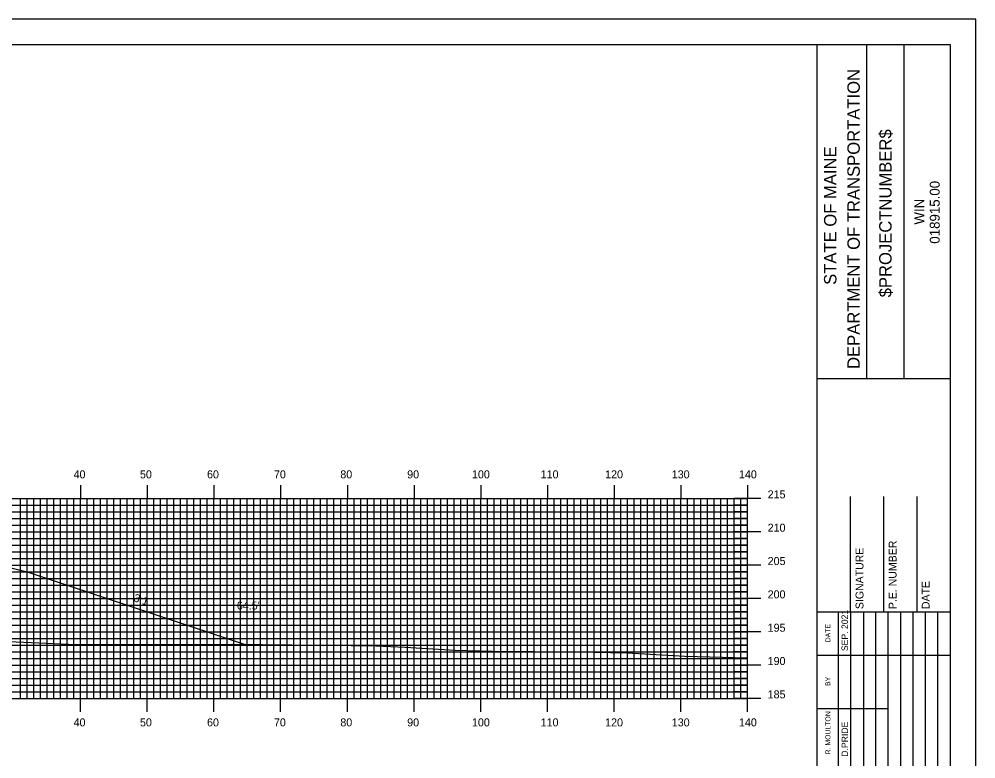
# Model space of a CAD drawing. Extents: x 1806651 to 1806995, y 442591 to 442811.
# Drawn here: x 1806848.1 to 1806991.5, y 442699.6 to 442810.5 of the extents above; entities that cross this region are included whole.
import ezdxf

# ---------------------------------------------------------------- set-up
doc = ezdxf.new("R2010")
doc.units = 0
for name, color, linetype in [('ANNOTATION', 7, 'Continuous'), ('BORDER', 7, 'Continuous'), ('D_Roadway_Centerline', 7, 'Continuous'), ('D_Roadway_SlopeLines', 7, 'Continuous'), ('D_Text_Standard', 7, 'Continuous'), ('H_V ANNOTATION', 7, 'Continuous'), ('MAJOR', 7, 'Continuous'), ('MINOR', 7, 'Continuous'), ('PLOT BOUNDARY', 7, 'Continuous'), ('S_Roadway_Centerline', 7, 'Continuous')]:
    doc.layers.add(name, color=color, linetype=linetype)

msp = doc.modelspace()

# ---------------------------------------------------------------- linework, layer by layer
at = {"layer": 'BORDER'}
for p, q in [((1806967.65, 442596.67), (1806967.65, 442806.67)), ((1806975.1, 442756.66), (1806975.1, 442806.66)), ((1806980.69, 442756.66), (1806980.69, 442806.66)), ((1806967.65, 442756.65), (1806987.65, 442756.65)), ((1806972.65, 442721.67), (1806972.65, 442738.97)), ((1806977.65, 442721.67), (1806977.65, 442738.97)), ((1806982.65, 442721.67), (1806982.65, 442738.97)), ((1806967.65, 442721.67), (1806987.65, 442721.67))]:
    msp.add_line(p, q, dxfattribs=at)
msp.add_lwpolyline([(1806667.65, 442596.67), (1806987.65, 442596.67), (1806987.65, 442806.67), (1806667.65, 442806.67)], close=True, dxfattribs=at)
for points in [[(1806970.88, 442715.17), (1806970.88, 442721.67)], [(1806972.74, 442686.68), (1806972.74, 442721.67)], [(1806974.6, 442721.67), (1806974.6, 442686.68)], [(1806976.47, 442686.68), (1806976.47, 442721.67)], [(1806978.33, 442686.68), (1806978.33, 442721.67)], [(1806980.19, 442686.68), (1806980.19, 442721.67)], [(1806982.06, 442686.68), (1806982.06, 442721.67)], [(1806983.92, 442686.68), (1806983.92, 442721.67)], [(1806985.78, 442686.68), (1806985.78, 442721.67)], [(1806970.88, 442686.68), (1806970.88, 442720.26)], [(1806967.65, 442715.17), (1806987.65, 442715.17)], [(1806967.65, 442707.17), (1806970.88, 442707.17)], [(1806970.88, 442707.17), (1806978.33, 442707.17)]]:
    msp.add_lwpolyline(points, dxfattribs=at)
at = {"layer": 'D_Roadway_Centerline'}
msp.add_lwpolyline([(1806757.75, 442718.48), (1806785.25, 442727.65), (1806787.07, 442728.1), (1806797.25, 442730.65), (1806805.25, 442730.97), (1806817.25, 442731.21), (1806829.25, 442730.97), (1806837.25, 442730.65), (1806847.42, 442728.1), (1806849.25, 442727.65), (1806881.77, 442716.8)], dxfattribs=at)
at = {"layer": 'D_Roadway_SlopeLines'}
msp.add_lwpolyline([(1806837.25, 442730.65), (1806849.25, 442727.65), (1806881.77, 442716.8)], dxfattribs=at)
at = {"layer": 'MAJOR'}
for p, q in [((1806857.25, 442740.67), (1806857.25, 442738.67)), ((1806867.25, 442740.67), (1806867.25, 442738.67)), ((1806877.25, 442740.67), (1806877.25, 442738.67)), ((1806887.25, 442740.67), (1806887.25, 442738.67)), ((1806897.25, 442740.67), (1806897.25, 442738.67)), ((1806907.25, 442740.67), (1806907.25, 442738.67)), ((1806917.25, 442740.67), (1806917.25, 442738.67)), ((1806927.25, 442740.67), (1806927.25, 442738.67)), ((1806937.25, 442740.67), (1806937.25, 442738.67)), ((1806947.25, 442740.67), (1806947.25, 442738.67)), ((1806957.25, 442740.67), (1806957.25, 442738.67)), ((1806677.25, 442738.67), (1806957.25, 442738.67)), ((1806677.25, 442738.67), (1806957.25, 442738.67)), ((1806857.25, 442708.67), (1806857.25, 442738.67)), ((1806867.25, 442708.67), (1806867.25, 442738.67)), ((1806877.25, 442708.67), (1806877.25, 442738.67)), ((1806887.25, 442708.67), (1806887.25, 442738.67)), ((1806897.25, 442708.67), (1806897.25, 442738.67)), ((1806907.25, 442708.67), (1806907.25, 442738.67)), ((1806917.25, 442708.67), (1806917.25, 442738.67)), ((1806927.25, 442708.67), (1806927.25, 442738.67)), ((1806937.25, 442708.67), (1806937.25, 442738.67)), ((1806947.25, 442708.67), (1806947.25, 442738.67)), ((1806959.25, 442738.67), (1806955.24, 442738.67)), ((1806957.25, 442708.67), (1806957.25, 442738.67)), ((1806957.25, 442708.67), (1806957.25, 442738.67)), ((1806677.25, 442733.67), (1806957.25, 442733.67)), ((1806959.25, 442733.67), (1806955.24, 442733.67)), ((1806677.25, 442728.67), (1806957.25, 442728.67)), ((1806959.25, 442728.67), (1806955.24, 442728.67)), ((1806677.25, 442723.67), (1806957.25, 442723.67)), ((1806959.25, 442723.67), (1806955.24, 442723.67)), ((1806677.25, 442718.67), (1806957.25, 442718.67)), ((1806959.25, 442718.67), (1806955.24, 442718.67)), ((1806677.25, 442713.67), (1806957.25, 442713.67)), ((1806959.25, 442713.67), (1806955.24, 442713.67)), ((1806677.25, 442708.67), (1806957.25, 442708.67)), ((1806677.25, 442708.67), (1806957.25, 442708.67)), ((1806857.25, 442706.66), (1806857.25, 442708.67)), ((1806867.25, 442706.66), (1806867.25, 442708.67)), ((1806877.25, 442706.66), (1806877.25, 442708.67)), ((1806887.25, 442706.66), (1806887.25, 442708.67)), ((1806897.25, 442706.66), (1806897.25, 442708.67)), ((1806907.25, 442706.66), (1806907.25, 442708.67)), ((1806917.25, 442706.66), (1806917.25, 442708.67)), ((1806927.25, 442706.66), (1806927.25, 442708.67)), ((1806937.25, 442706.66), (1806937.25, 442708.67)), ((1806947.25, 442706.66), (1806947.25, 442708.67)), ((1806959.25, 442708.67), (1806955.24, 442708.67)), ((1806957.25, 442706.66), (1806957.25, 442708.67))]:
    msp.add_line(p, q, dxfattribs=at)
at = {"layer": 'MINOR'}
for p, q in [((1806848.25, 442708.67), (1806848.25, 442738.67)), ((1806849.25, 442708.67), (1806849.25, 442738.67)), ((1806850.25, 442708.67), (1806850.25, 442738.67)), ((1806851.25, 442708.67), (1806851.25, 442738.67)), ((1806852.25, 442708.67), (1806852.25, 442738.67)), ((1806853.25, 442708.67), (1806853.25, 442738.67)), ((1806854.25, 442708.67), (1806854.25, 442738.67)), ((1806855.25, 442708.67), (1806855.25, 442738.67)), ((1806856.25, 442708.67), (1806856.25, 442738.67)), ((1806858.25, 442708.67), (1806858.25, 442738.67)), ((1806859.25, 442708.67), (1806859.25, 442738.67)), ((1806860.25, 442708.67), (1806860.25, 442738.67)), ((1806861.25, 442708.67), (1806861.25, 442738.67)), ((1806862.25, 442708.67), (1806862.25, 442738.67)), ((1806863.25, 442708.67), (1806863.25, 442738.67)), ((1806864.25, 442708.67), (1806864.25, 442738.67)), ((1806865.25, 442708.67), (1806865.25, 442738.67)), ((1806866.25, 442708.67), (1806866.25, 442738.67)), ((1806868.25, 442708.67), (1806868.25, 442738.67)), ((1806869.25, 442708.67), (1806869.25, 442738.67)), ((1806870.25, 442708.67), (1806870.25, 442738.67)), ((1806871.25, 442708.67), (1806871.25, 442738.67)), ((1806872.25, 442708.67), (1806872.25, 442738.67)), ((1806873.25, 442708.67), (1806873.25, 442738.67)), ((1806874.25, 442708.67), (1806874.25, 442738.67)), ((1806875.25, 442708.67), (1806875.25, 442738.67)), ((1806876.25, 442708.67), (1806876.25, 442738.67)), ((1806878.25, 442708.67), (1806878.25, 442738.67)), ((1806879.25, 442708.67), (1806879.25, 442738.67)), ((1806880.25, 442708.67), (1806880.25, 442738.67)), ((1806881.25, 442708.67), (1806881.25, 442738.67)), ((1806882.25, 442708.67), (1806882.25, 442738.67)), ((1806883.25, 442708.67), (1806883.25, 442738.67)), ((1806884.25, 442708.67), (1806884.25, 442738.67)), ((1806885.25, 442708.67), (1806885.25, 442738.67)), ((1806886.25, 442708.67), (1806886.25, 442738.67)), ((1806888.25, 442708.67), (1806888.25, 442738.67)), ((1806889.25, 442708.67), (1806889.25, 442738.67)), ((1806890.25, 442708.67), (1806890.25, 442738.67)), ((1806891.25, 442708.67), (1806891.25, 442738.67)), ((1806892.25, 442708.67), (1806892.25, 442738.67)), ((1806893.25, 442708.67), (1806893.25, 442738.67)), ((1806894.25, 442708.67), (1806894.25, 442738.67)), ((1806895.25, 442708.67), (1806895.25, 442738.67)), ((1806896.25, 442708.67), (1806896.25, 442738.67)), ((1806898.25, 442708.67), (1806898.25, 442738.67)), ((1806899.25, 442708.67), (1806899.25, 442738.67)), ((1806900.25, 442708.67), (1806900.25, 442738.67)), ((1806901.25, 442708.67), (1806901.25, 442738.67)), ((1806902.25, 442708.67), (1806902.25, 442738.67)), ((1806903.25, 442708.67), (1806903.25, 442738.67)), ((1806904.25, 442708.67), (1806904.25, 442738.67)), ((1806905.25, 442708.67), (1806905.25, 442738.67)), ((1806906.25, 442708.67), (1806906.25, 442738.67)), ((1806908.25, 442708.67), (1806908.25, 442738.67)), ((1806909.25, 442708.67), (1806909.25, 442738.67)), ((1806910.25, 442708.67), (1806910.25, 442738.67)), ((1806911.25, 442708.67), (1806911.25, 442738.67)), ((1806912.25, 442708.67), (1806912.25, 442738.67)), ((1806913.25, 442708.67), (1806913.25, 442738.67)), ((1806914.25, 442708.67), (1806914.25, 442738.67)), ((1806915.25, 442708.67), (1806915.25, 442738.67)), ((1806916.25, 442708.67), (1806916.25, 442738.67)), ((1806918.25, 442708.67), (1806918.25, 442738.67)), ((1806919.25, 442708.67), (1806919.25, 442738.67)), ((1806920.25, 442708.67), (1806920.25, 442738.67)), ((1806921.25, 442708.67), (1806921.25, 442738.67)), ((1806922.25, 442708.67), (1806922.25, 442738.67)), ((1806923.25, 442708.67), (1806923.25, 442738.67)), ((1806924.25, 442708.67), (1806924.25, 442738.67)), ((1806925.25, 442708.67), (1806925.25, 442738.67)), ((1806926.25, 442708.67), (1806926.25, 442738.67)), ((1806928.25, 442708.67), (1806928.25, 442738.67)), ((1806929.25, 442708.67), (1806929.25, 442738.67)), ((1806930.25, 442708.67), (1806930.25, 442738.67)), ((1806931.25, 442708.67), (1806931.25, 442738.67)), ((1806932.25, 442708.67), (1806932.25, 442738.67)), ((1806933.25, 442708.67), (1806933.25, 442738.67)), ((1806934.25, 442708.67), (1806934.25, 442738.67)), ((1806935.25, 442708.67), (1806935.25, 442738.67)), ((1806936.25, 442708.67), (1806936.25, 442738.67)), ((1806938.25, 442708.67), (1806938.25, 442738.67)), ((1806939.25, 442708.67), (1806939.25, 442738.67)), ((1806940.25, 442708.67), (1806940.25, 442738.67)), ((1806941.25, 442708.67), (1806941.25, 442738.67)), ((1806942.25, 442708.67), (1806942.25, 442738.67)), ((1806943.25, 442708.67), (1806943.25, 442738.67)), ((1806944.25, 442708.67), (1806944.25, 442738.67)), ((1806945.25, 442708.67), (1806945.25, 442738.67)), ((1806946.25, 442708.67), (1806946.25, 442738.67)), ((1806948.25, 442708.67), (1806948.25, 442738.67)), ((1806949.25, 442708.67), (1806949.25, 442738.67)), ((1806950.25, 442708.67), (1806950.25, 442738.67)), ((1806951.25, 442708.67), (1806951.25, 442738.67)), ((1806952.25, 442708.67), (1806952.25, 442738.67)), ((1806953.25, 442708.67), (1806953.25, 442738.67)), ((1806954.25, 442708.67), (1806954.25, 442738.67)), ((1806955.25, 442708.67), (1806955.25, 442738.67)), ((1806956.25, 442708.67), (1806956.25, 442738.67)), ((1806677.25, 442737.67), (1806957.25, 442737.67)), ((1806957.25, 442737.67), (1806955.24, 442737.67)), ((1806677.25, 442736.67), (1806957.25, 442736.67)), ((1806677.25, 442735.67), (1806957.25, 442735.67)), ((1806957.25, 442736.67), (1806955.24, 442736.67)), ((1806957.25, 442735.67), (1806955.24, 442735.67)), ((1806677.25, 442734.67), (1806957.25, 442734.67)), ((1806957.25, 442734.67), (1806955.24, 442734.67)), ((1806677.25, 442732.67), (1806957.25, 442732.67)), ((1806957.25, 442732.67), (1806955.24, 442732.67)), ((1806677.25, 442731.67), (1806957.25, 442731.67)), ((1806957.25, 442731.67), (1806955.24, 442731.67)), ((1806677.25, 442730.67), (1806957.25, 442730.67)), ((1806957.25, 442730.67), (1806955.24, 442730.67)), ((1806677.25, 442729.67), (1806957.25, 442729.67)), ((1806957.25, 442729.67), (1806955.24, 442729.67)), ((1806677.25, 442727.67), (1806957.25, 442727.67)), ((1806957.25, 442727.67), (1806955.24, 442727.67)), ((1806677.25, 442726.67), (1806957.25, 442726.67)), ((1806677.25, 442725.67), (1806957.25, 442725.67)), ((1806957.25, 442726.67), (1806955.24, 442726.67)), ((1806957.25, 442725.67), (1806955.24, 442725.67)), ((1806677.25, 442724.67), (1806957.25, 442724.67)), ((1806957.25, 442724.67), (1806955.24, 442724.67)), ((1806677.25, 442722.67), (1806957.25, 442722.67)), ((1806957.25, 442722.67), (1806955.24, 442722.67)), ((1806677.25, 442721.67), (1806957.25, 442721.67)), ((1806957.25, 442721.67), (1806955.24, 442721.67)), ((1806677.25, 442720.67), (1806957.25, 442720.67)), ((1806677.25, 442719.67), (1806957.25, 442719.67)), ((1806957.25, 442720.67), (1806955.24, 442720.67)), ((1806957.25, 442719.67), (1806955.24, 442719.67)), ((1806677.25, 442717.67), (1806957.25, 442717.67)), ((1806957.25, 442717.67), (1806955.24, 442717.67)), ((1806677.25, 442716.67), (1806957.25, 442716.67)), ((1806677.25, 442715.67), (1806957.25, 442715.67)), ((1806957.25, 442716.67), (1806955.24, 442716.67)), ((1806957.25, 442715.67), (1806955.24, 442715.67)), ((1806677.25, 442714.67), (1806957.25, 442714.67)), ((1806957.25, 442714.67), (1806955.24, 442714.67)), ((1806677.25, 442712.67), (1806957.25, 442712.67)), ((1806957.25, 442712.67), (1806955.24, 442712.67)), ((1806677.25, 442711.67), (1806957.25, 442711.67)), ((1806957.25, 442711.67), (1806955.24, 442711.67)), ((1806677.25, 442710.67), (1806957.25, 442710.67)), ((1806677.25, 442709.67), (1806957.25, 442709.67)), ((1806957.25, 442710.67), (1806955.24, 442710.67)), ((1806957.25, 442709.67), (1806955.24, 442709.67))]:
    msp.add_line(p, q, dxfattribs=at)
at = {"layer": 'PLOT BOUNDARY'}
msp.add_lwpolyline([(1806651.46, 442590.55), (1806991.46, 442590.55), (1806991.46, 442810.55), (1806651.46, 442810.55)], close=True, dxfattribs=at)
at = {"layer": 'S_Roadway_Centerline'}
msp.add_lwpolyline([(1806834.08, 442717.73), (1806855.48, 442716.81), (1806856.23, 442716.76), (1806856.8, 442716.76), (1806880.09, 442716.82), (1806897.81, 442716.62), (1806901.51, 442716.56), (1806905.93, 442716.33), (1806913.4, 442715.88), (1806919.03, 442715.76), (1806931.77, 442715.67), (1806939.2, 442715.51), (1806947.85, 442714.98), (1806957.25, 442714.75)], dxfattribs=at)

# ---------------------------------------------------------------- texts
at = {"layer": 'ANNOTATION'}
msp.add_text('3:1', height=1.2, rotation=341.5652, dxfattribs=at).set_placement((1806865.11, 442723.27))
at = {"layer": 'BORDER'}
for s, height, p in [('DEPARTMENT OF TRANSPORTATION', 1.8635, (1806974.06, 442758.08)), ('$PROJECTNUMBER$', 1.8635, (1806978.83, 442768.82)), ('STATE OF MAINE', 1.8635, (1806970.56, 442770.69)), ('018915.00', 1.491, (1806986.04, 442776.86)), ('WIN', 1.491, (1806983.72, 442779.73)), ('SIGNATURE', 1.181, (1806974.61, 442722.06)), ('P.E. NUMBER', 1.1811, (1806979.57, 442722.06)), ('DATE', 1.181, (1806984.53, 442722.06)), ('SEP. 2021', 0.969, (1806972.29, 442715.76)), ('DATE', 0.743, (1806969.65, 442717.08)), ('BY', 0.743, (1806969.65, 442710.54)), ('R. MOULTON', 0.745, (1806969.66, 442700.28)), ('D.PRIDE', 0.969, (1806972.29, 442699.92))]:
    msp.add_text(s, height=height, rotation=90, dxfattribs=at).set_placement(p)
at = {"layer": 'D_Text_Standard'}
msp.add_text("64.5'", height=1.2, dxfattribs=at).set_placement((1806880.69, 442722))
at = {"layer": 'H_V ANNOTATION'}
for s, p in [('40', (1806856.22, 442741.67)), ('50', (1806866.17, 442741.67)), ('60', (1806876.22, 442741.67)), ('70', (1806886.25, 442741.67)), ('80', (1806896.2, 442741.67)), ('90', (1806906.22, 442741.67)), ('100', (1806915.93, 442741.67)), ('110', (1806926.23, 442741.67)), ('120', (1806935.89, 442741.67)), ('130', (1806945.88, 442741.67)), ('140', (1806955.95, 442741.67)), ('215', (1806960.25, 442738.67)), ('210', (1806960.25, 442733.67)), ('205', (1806960.25, 442728.67)), ('200', (1806960.25, 442723.67)), ('195', (1806960.25, 442718.67)), ('190', (1806960.25, 442713.67)), ('185', (1806960.25, 442708.67)), ('40', (1806856.22, 442704.47)), ('50', (1806866.17, 442704.47)), ('60', (1806876.22, 442704.47)), ('70', (1806886.25, 442704.47)), ('80', (1806896.2, 442704.47)), ('90', (1806906.22, 442704.47)), ('100', (1806915.93, 442704.47)), ('110', (1806926.23, 442704.47)), ('120', (1806935.89, 442704.47)), ('130', (1806945.88, 442704.47)), ('140', (1806955.95, 442704.47))]:
    msp.add_text(s, height=1.2, dxfattribs=at).set_placement(p)

doc.saveas('drawing.dxf')
